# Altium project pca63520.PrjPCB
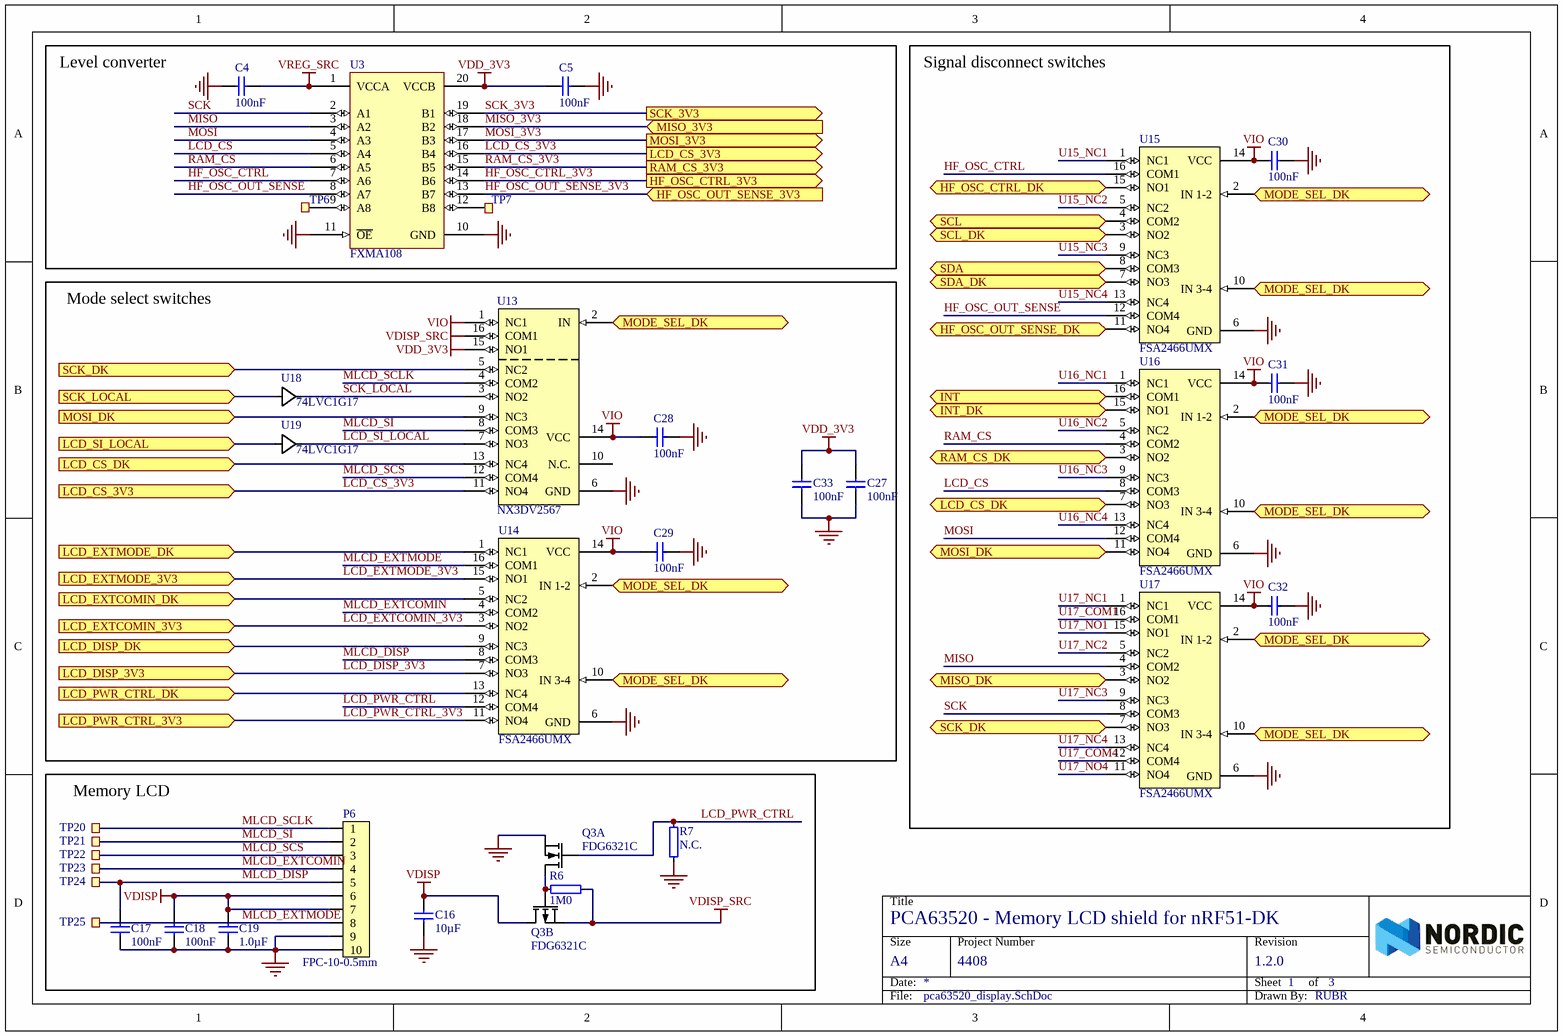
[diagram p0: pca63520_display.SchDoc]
3 sheets, 154 parts. Net scope: flat (ports and power ports of the same name join across sheets).
Board file: 400139.PcbDoc
Sheets:
  pca63520_display.SchDoc
  pca63520_interface.SchDoc
  pca63520_support_circuitry.SchDoc

## Sheet pca63520_display.SchDoc: PCA63520 - Memory LCD shield for nRF51-DK
size A4; Revision: 1.2.0; SheetNumber: 1; SheetTotal: 3; DrawnBy: RUBR; ProjectNumber: 4408; DocumentSize: A4; PCBRevision: 0233RUBR; PCAName: PCA63520; PCBNumber: 400139

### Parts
C4  100nF  [CAPC1005X04L]
C5  100nF  [CAPC1005X04L]
C16  10µF  [CAPC2012X11L]
C17  100nF  [CAPC1005X04L]
C18  100nF  [CAPC1005X04L]
C19  1.0µF  [CAPC1608X06L]
C27  100nF  [CAPC1005X04L]
C28  100nF  [CAPC1005X04L]
C29  100nF  [CAPC1005X04L]
C30  100nF  [CAPC1005X04L]
C31  100nF  [CAPC1005X04L]
C32  100nF  [CAPC1005X04L]
C33  100nF  [CAPC1005X04L]
P6  FPC-10-0.5mm  [Molex 51441-1072]
Q3  FDG6321C  [SOT65P210X100-6N]  (parts A,B of 2)
R6  1M0  [RESC1005X04L]
R7  N.C.  [RESC1005X04L]
TP6  Ø1.0mm,SMD  [TP_SMD_Ø1.0mm]  (value not drawn)  (no BOM)
TP7  Ø1.0mm,SMD  [TP_SMD_Ø1.0mm]  (value not drawn)  (no BOM)
TP20  Ø1.0mm,SMD  [TP_SMD_Ø1.0mm]  (value not drawn)  (no BOM)
TP21  Ø1.0mm,SMD  [TP_SMD_Ø1.0mm]  (value not drawn)  (no BOM)
TP22  Ø1.0mm,SMD  [TP_SMD_Ø1.0mm]  (value not drawn)  (no BOM)
TP23  Ø1.0mm,SMD  [TP_SMD_Ø1.0mm]  (value not drawn)  (no BOM)
TP24  Ø1.0mm,SMD  [TP_SMD_Ø1.0mm]  (value not drawn)  (no BOM)
TP25  Ø1.0mm,SMD  [TP_SMD_Ø1.0mm]  (value not drawn)  (no BOM)
U3  FXMA108  [QFN50P450X250X80_HS-21N]
U13  NX3DV2567  [XQFN40P180X260X50-16N]
U14  FSA2466UMX  [XQFN40P180X260X50-16N]
U15  FSA2466UMX  [XQFN40P180X260X50-16N]
U16  FSA2466UMX  [XQFN40P180X260X50-16N]
U17  FSA2466UMX  [XQFN40P180X260X50-16N]
U18  74LVC1G17  [SOT-353]
U19  74LVC1G17  [SOT-353]

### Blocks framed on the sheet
Level converter: C4 C5 TP6 TP7 U3
Signal disconnect switches: C30-C32 U15-U17
Mode select switches: C27-C29 C33 U13 U14 U18 U19
Memory LCD: C16-C19 P6 Q3 R6 R7 TP20-TP25

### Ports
HF_OSC_CTRL_3V3 (out), HF_OSC_CTRL_DK (in), HF_OSC_OUT_SENSE_3V3 (in), HF_OSC_OUT_SENSE_DK (out), INT (in), INT_DK (out), LCD_CS_3V3 (in), LCD_CS_3V3 (out), LCD_CS_DK (in), LCD_DISP_3V3 (in), LCD_DISP_DK (in), LCD_EXTCOMIN_3V3 (in), LCD_EXTCOMIN_DK (in), LCD_EXTMODE_3V3 (in), LCD_EXTMODE_DK (in), LCD_PWR_CTRL_3V3 (in), LCD_PWR_CTRL_DK (in), LCD_SI_LOCAL (in), MISO_3V3 (in), MISO_DK (out), MODE_SEL_DK (in), MOSI_3V3 (out), MOSI_DK (in), RAM_CS_3V3 (out), RAM_CS_DK (in), SCK_3V3 (out), SCK_DK (in), SCK_LOCAL (in), SCL (out), SCL_DK (in), SDA (bidir), SDA_DK (bidir)

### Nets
GND: C4.1 C5.1 C16.1 C17.1 C18.1 C19.1 C27.2 C28.1 C29.1 C30.1 C31.1 C32.1 C33.2 P6.9 P6.10 Q3.1(S1) R7.2 U3.10(GND) U3.11(~{OE}) U13.6(GND) U14.6(GND) U15.6(GND) U16.6(GND) U17.6(GND) U18.3(GND) U19.3(GND)
VDD_3V3: C5.2 C27.1 C33.1 U3.20(VCCB) U13.15(NO1) U18.5(VDD) U19.5(VDD)
VDISP: C16.2 C18.2 C19.2 P6.6 P6.7 Q3.3(D2)
VDISP_SRC: Q3.4(S2) R6.1 U13.16(COM1)
VIO: C28.2 C29.2 C30.2 C31.2 C32.2 U13.1(NC1) U13.14(VCC) U14.14(VCC) U15.14(VCC) U16.14(VCC) U17.14(VCC)
VREG_SRC: C4.2 U3.1(VCCA)
A2: U14.5(NC2) ; port LCD_EXTCOMIN_DK
A3: U14.1(NC1) ; port LCD_EXTMODE_DK
A4: U14.9(NC3) ; port LCD_DISP_DK
A5: U14.13(NC4) ; port LCD_PWR_CTRL_DK
AREF: U13.2(IN) U14.2(IN_1-2) U14.10(IN_3-4) U15.2(IN_1-2) U15.10(IN_3-4) U16.2(IN_1-2) U16.10(IN_3-4) U17.2(IN_1-2) U17.10(IN_3-4) ; port MODE_SEL_DK
D2: U15.15(NO1) ; port HF_OSC_CTRL_DK
D3: U15.11(NO4) ; port HF_OSC_OUT_SENSE_DK
D4: U16.15(NO1) ; port INT_DK
D9: U16.3(NO2) ; port RAM_CS_DK
D10 (SS): U13.13(NC4) U16.7(NO3) ; port LCD_CS_DK
D11 (MOSI): U13.9(NC3) U16.11(NO4) ; port MOSI_DK
D12 (MISO): U17.3(NO2) ; port MISO_DK
D13 (SCK): U13.5(NC2) U17.7(NO3) ; port SCK_DK
HF_OSC_CTRL: U3.7(A6) U15.16(COM1)
HF_OSC_CTRL_3V3: U3.14(B6) ; port HF_OSC_CTRL_3V3
HF_OSC_OUT_SENSE: U3.8(A7) U15.12(COM4)
HF_OSC_OUT_SENSE_3V3: U3.13(B7) ; port HF_OSC_OUT_SENSE_3V3
INT: U16.16(COM1) ; port INT
LCD_CS: U3.5(A4) U16.8(COM3)
LCD_CS_3V3: U3.16(B4) U13.11(NO4) ; port LCD_CS_3V3
LCD_DISP_3V3: U14.7(NO3) ; port LCD_DISP_3V3
LCD_EXTCOMIN_3V3: U14.3(NO2) ; port LCD_EXTCOMIN_3V3
LCD_EXTMODE_3V3: U14.15(NO1) ; port LCD_EXTMODE_3V3
LCD_PWR_CTRL: Q3.2(G1) R7.1 U14.12(COM4)
LCD_PWR_CTRL_3V3: U14.11(NO4) ; port LCD_PWR_CTRL_3V3
LCD_SI_LOCAL: U13.7(NO3) U19.4(Y)
MISO: U3.3(A2) U17.4(COM2)
MISO_3V3: U3.18(B2) ; port MISO_3V3
MLCD_DISP: C17.2 P6.5 TP24.1 U14.8(COM3)
MLCD_EXTCOMIN: P6.4 TP23.1 U14.4(COM2)
MLCD_EXTMODE: P6.8 TP25.1 U14.16(COM1)
MLCD_SCLK: P6.1 TP20.1 U13.4(COM2)
MLCD_SCS: P6.3 TP22.1 U13.12(COM4)
MLCD_SI: P6.2 TP21.1 U13.8(COM3)
MOSI: U3.4(A3) U16.12(COM4)
MOSI_3V3: U3.17(B3) ; port MOSI_3V3
RAM_CS: U3.6(A5) U16.4(COM2)
RAM_CS_3V3: U3.15(B5) ; port RAM_CS_3V3
SCK: U3.2(A1) U17.8(COM3)
SCK_3V3: U3.19(B1) ; port SCK_3V3
SCK_LOCAL: U13.3(NO2) U18.4(Y)
SCL': U15.4(COM2) ; port SCL
SCL_DK: U15.3(NO2) ; port SCL_DK
SDA': U15.8(COM3) ; port SDA
SDA_DK: U15.7(NO3) ; port SDA_DK
U15_NC1: U15.1(NC1)
U15_NC2: U15.5(NC2)
U15_NC3: U15.9(NC3)
U15_NC4: U15.13(NC4)
U16_NC1: U16.1(NC1)
U16_NC2: U16.5(NC2)
U16_NC3: U16.9(NC3)
U16_NC4: U16.13(NC4)
U17_COM1: U17.16(COM1)
U17_COM4: U17.12(COM4)
U17_NC1: U17.1(NC1)
U17_NC2: U17.5(NC2)
U17_NC3: U17.9(NC3)
U17_NC4: U17.13(NC4)
U17_NO1: U17.15(NO1)
U17_NO4: U17.11(NO4)
NetQ3_5: Q3.5(G2) Q3.6(D1) R6.2
NetTP6_1: TP6.1 U3.9(A8)
NetTP7_1: TP7.1 U3.12(B8)
NetU5_12: U19.2(A) ; port LCD_SI_LOCAL
NetU5_15: U18.2(A) ; port SCK_LOCAL

Not connected (* = marked no-connect by the designer): U13 10(N.C.); U18 1(N.C.); U19 1(N.C.)

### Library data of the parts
C4 C5 C17 C18 C27-C33 = C0402-100n: Capacitor, X7R, ±10%; Note: 16V; Artikkelnr Noca: 20039200; Artikkelnr Simpro: N.A.
C16 = C0805-10µ: Capacitor, X5R, ±10%; Note: 16V; Artikkelnr Noca: 20039243; Artikkelnr Simpro: N.A.
C19 = C0603-1µ0: Capacitor, X7R, ±10%; Note: 16V; Artikkelnr Noca: 20039335; Artikkelnr Simpro: N.A.
P6 = Molex 51441-1072: FFC/FPC Connector, Right-Angle, SMD, ZIF, Bottom Contacts, 10-way, Gold; Manufacturer: Molex; 2nd source part number: 538-51441-1072; Artikkelnr Noca: N.A.
Q3 = FDG6321C: Fairchild, FDG6321C, Dual N & P Channel Digital FET; 2nd source part number: FDG6321CCT-ND; Artikkelnr Noca: 35029089; Artikkelnr Simpro: N.A.
R6 = R0402-1M0: Resistor, ±1%, 0.063W; Note: Chip Res 1%; Artikkelnr Noca: 27049145; Artikkelnr Simpro: N.A.; Value Ohm: 1000000
R7 = R0402-N.C.: Not mounted; Note: Chip Res; Artikkelnr Noca: N.A.; Assembly: Not mounted
TP6 TP7 TP20-TP25 = TP_SMD_Ø1.0MM: 1.0mm circular SMD testpad; Manufacturer: Nordic Semiconductor; Artikkelnr Noca: N.A.
U3 = FXMA108BQX: 8-bit bidirectional voltage-level translator with auto-direction sensing; Manufacturer: Fairchild Semiconductor; 2nd source part number: 512-FXMA108BQX; Note: Translator, Bidirectional; Artikkelnr Noca: N.A.
U13 = NX3DV2567GU: Low-ohmic four-pole double-throw analog switch; Manufacturer: NXP Semiconductors; 2nd source part number: 771-NX3DV2567GU115; Artikkelnr Noca: N.A.
U14-U17 = FSA2466UMX: Data / Audio Low-Voltage Dual DPDT Analog Switch; Manufacturer: Fairchild Semiconductor; 2nd source part number: 512-FSA2466UMX; Artikkelnr Noca: N.A.
U18 U19 = 74LVC1G17SE: Single schmitt-trigger buffer with standard push-pull output; Manufacturer: Diodes; 2nd source part number: 189-3834; Artikkelnr Noca: 15049066; Artikkelnr Simpro: N.A.

## Sheet pca63520_interface.SchDoc: PCA63520 - Memory LCD shield for nRF51-DK
size A4; Revision: 1.2.0; SheetNumber: 2; SheetTotal: 3; DrawnBy: RUBR; ProjectNumber: 4408; DocumentSize: A4; PCBRevision: 0233RUBR; PCAName: PCA63520; PCBNumber: 400139
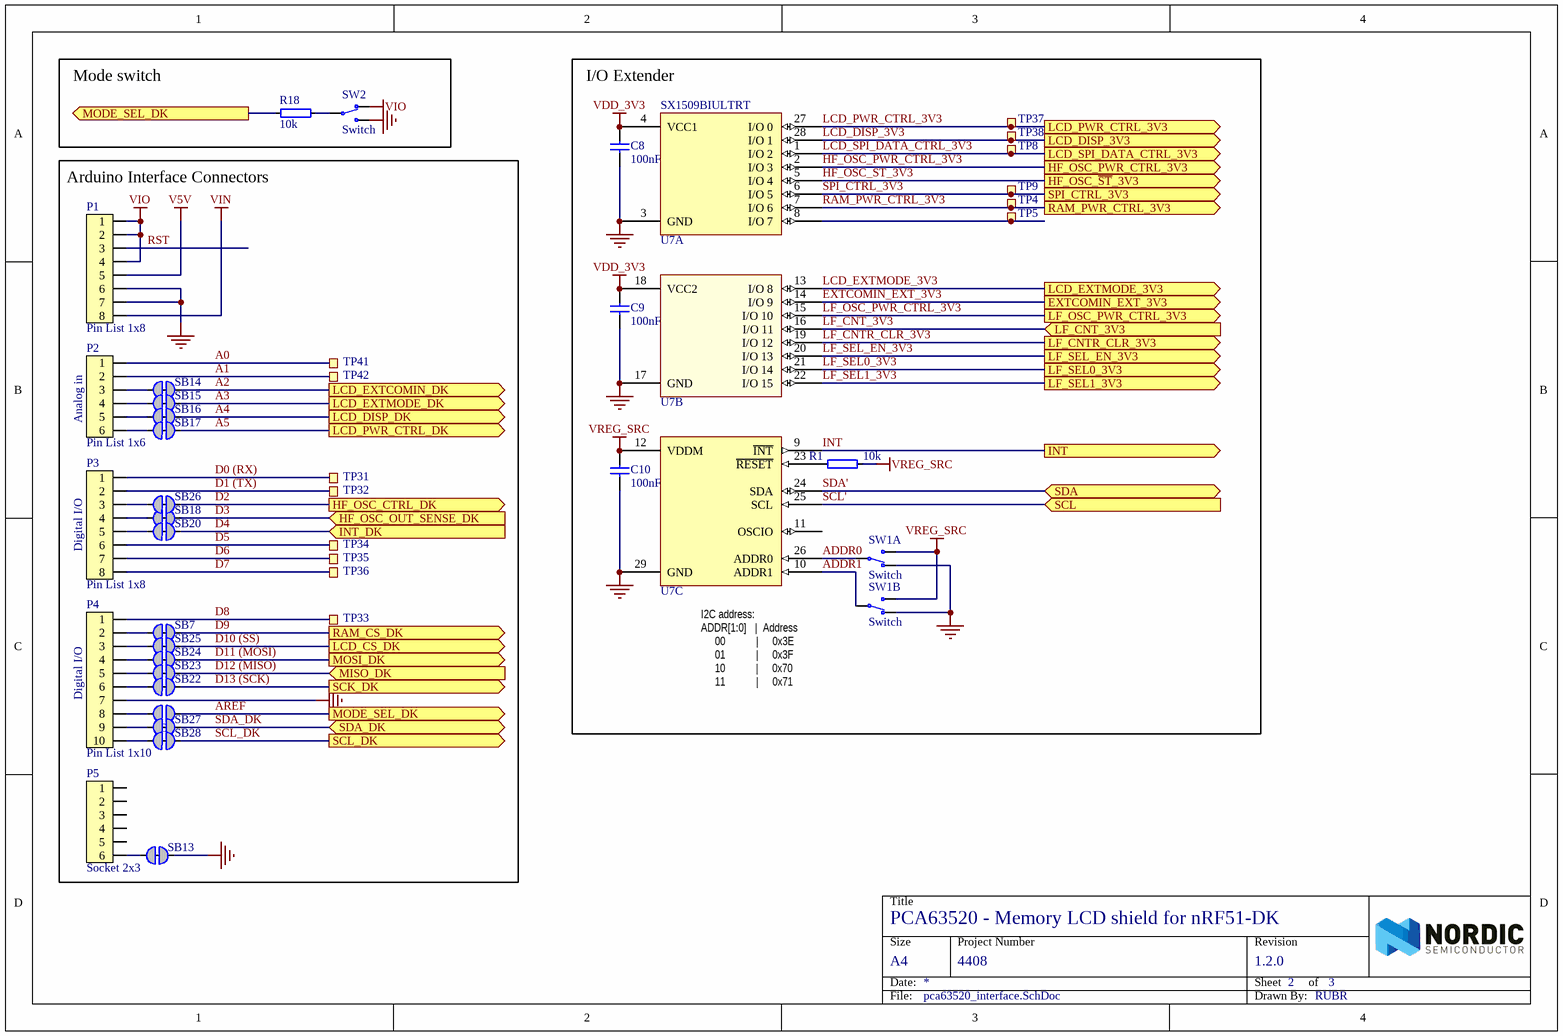
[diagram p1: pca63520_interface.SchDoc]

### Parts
C8  100nF  [CAPC1005X04L]
C9  100nF  [CAPC1005X04L]
C10  100nF  [CAPC1005X04L]
P1  Pin List 1x8  [LIST_1x8_SMD]
P2  Pin List 1x6  [LIST_1x6_SMD]
P3  Pin List 1x8  [LIST_1x8_SMD]
P4  Pin List 1x10  [LIST_1x10_SMD]
P5  Socket 2x3  [SOCKET_2x3_SMD-2.54mm-bottom]
R1  10k  [RESC1005X04L]
R18  10k  [RESC1005X04L]
SB6  Solderbridge  [Solderbridge]  (value not drawn)  (no BOM)
SB7  Solderbridge  [Solderbridge_Shorted]  (value not drawn)  (net tie, no BOM)
SB13  Solderbridge  [Solderbridge_Shorted]  (value not drawn)  (net tie, no BOM)
SB14  Solderbridge  [Solderbridge_Shorted]  (value not drawn)  (net tie, no BOM)
SB15  Solderbridge  [Solderbridge_Shorted]  (value not drawn)  (net tie, no BOM)
SB16  Solderbridge  [Solderbridge_Shorted]  (value not drawn)  (net tie, no BOM)
SB17  Solderbridge  [Solderbridge_Shorted]  (value not drawn)  (net tie, no BOM)
SB18  Solderbridge  [Solderbridge_Shorted]  (value not drawn)  (net tie, no BOM)
SB20  Solderbridge  [Solderbridge_Shorted]  (value not drawn)  (net tie, no BOM)
SB22  Solderbridge  [Solderbridge_Shorted]  (value not drawn)  (net tie, no BOM)
SB23  Solderbridge  [Solderbridge_Shorted]  (value not drawn)  (net tie, no BOM)
SB24  Solderbridge  [Solderbridge_Shorted]  (value not drawn)  (net tie, no BOM)
SB25  Solderbridge  [Solderbridge_Shorted]  (value not drawn)  (net tie, no BOM)
SB26  Solderbridge  [Solderbridge_Shorted]  (value not drawn)  (net tie, no BOM)
SB27  Solderbridge  [Solderbridge_Shorted]  (value not drawn)  (net tie, no BOM)
SB28  Solderbridge  [Solderbridge_Shorted]  (value not drawn)  (net tie, no BOM)
SW1  Switch  [CAS-D20A]  (parts A,B of 2)
SW2  Switch  [CJS-120xA]
TP4  Ø1.0mm,SMD  [TP_SMD_Ø1.0mm]  (value not drawn)  (no BOM)
TP5  Ø1.0mm,SMD  [TP_SMD_Ø1.0mm]  (value not drawn)  (no BOM)
TP8  Ø1.0mm,SMD  [TP_SMD_Ø1.0mm]  (value not drawn)  (no BOM)
TP9  Ø1.0mm,SMD  [TP_SMD_Ø1.0mm]  (value not drawn)  (no BOM)
TP31  Ø1.0mm,SMD  [TP_SMD_Ø1.0mm]  (value not drawn)  (no BOM)
TP32  Ø1.0mm,SMD  [TP_SMD_Ø1.0mm]  (value not drawn)  (no BOM)
TP33  Ø1.0mm,SMD  [TP_SMD_Ø1.0mm]  (value not drawn)  (no BOM)
TP34  Ø1.0mm,SMD  [TP_SMD_Ø1.0mm]  (value not drawn)  (no BOM)
TP35  Ø1.0mm,SMD  [TP_SMD_Ø1.0mm]  (value not drawn)  (no BOM)
TP36  Ø1.0mm,SMD  [TP_SMD_Ø1.0mm]  (value not drawn)  (no BOM)
TP37  Ø1.0mm,SMD  [TP_SMD_Ø1.0mm]  (value not drawn)  (no BOM)
TP38  Ø1.0mm,SMD  [TP_SMD_Ø1.0mm]  (value not drawn)  (no BOM)
TP41  Ø1.0mm,SMD  [TP_SMD_Ø1.0mm]  (value not drawn)  (no BOM)
TP42  Ø1.0mm,SMD  [TP_SMD_Ø1.0mm]  (value not drawn)  (no BOM)
U7  SX1509BIULTRT  [QFN40P400X400X60_HS-29N]  (parts A,B,C of 3)

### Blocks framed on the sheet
Mode switch: R18 SW2
I/O Extender: C8-C10 R1 SW1 TP4 TP5 TP8 TP9 TP37 TP38 U7
Arduino Interface Connectors: P1-P5 SB6 SB7 SB13-SB18 SB20 SB22-SB28 TP31-TP36 TP41 TP42

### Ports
EXTCOMIN_EXT_3V3 (out), HF_OSC_CTRL_DK (out), HF_OSC_OUT_SENSE_DK (in), HF_OSC_PWR_CTRL_3V3 (out), HF_OSC_~{ST}_3V3 (out), INT (out), INT_DK (in), LCD_CS_DK (out), LCD_DISP_3V3 (out), LCD_DISP_DK (out), LCD_EXTCOMIN_DK (out), LCD_EXTMODE_3V3 (out), LCD_EXTMODE_DK (out), LCD_PWR_CTRL_3V3 (out), LCD_PWR_CTRL_DK (out), LCD_SPI_DATA_CTRL_3V3 (out), LF_CNT_3V3 (in), LF_CNTR_CLR_3V3 (out), LF_OSC_PWR_CTRL_3V3 (out), LF_SEL0_3V3 (out), LF_SEL1_3V3 (out), LF_SEL_EN_3V3 (out), MISO_DK (in), MODE_SEL_DK (out), MOSI_DK (out), RAM_CS_DK (out), RAM_PWR_CTRL_3V3 (out), SCK_DK (out), SCL (in), SCL_DK (out), SDA (bidir), SDA_DK (bidir), SPI_CTRL_3V3 (out)

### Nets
GND: C8.1 C9.1 C10.1 P1.6 P1.7 P4.7 SB13.1 SW1.3(N.C) SW1.6(N.C) SW2.3(N.O) U7.3(GND) U7.17(GND) U7.29(GND)
V5V: P1.5
VDD_3V3: C8.2 C9.2 U7.4(VCC1) U7.18(VCC2)
VIN: P1.8
VIO: P1.1 P1.2 P1.4 SW2.1(N.C)
VREG_SRC: C10.2 R1.2 SW1.1(N.O) SW1.4(N.O) U7.12(VDDM)
A0: P2.1 TP41.1
A1: P2.2 TP42.1
A2: SB14.1 ; port LCD_EXTCOMIN_DK
A3: SB15.1 ; port LCD_EXTMODE_DK
A4: SB16.1 ; port LCD_DISP_DK
A5: SB17.1 ; port LCD_PWR_CTRL_DK
ADDR0: SW1.2(COM) U7.26(ADDR0)
ADDR1: SW1.5(COM) U7.10(ADDR1)
AREF: R18.1 SB6.1 ; port MODE_SEL_DK
D0 (RX): P3.1 TP31.1
D1 (TX): P3.2 TP32.1
D2: SB26.1 ; port HF_OSC_CTRL_DK
D3: SB18.1 ; port HF_OSC_OUT_SENSE_DK
D4: SB20.1 ; port INT_DK
D5: P3.6 TP34.1
D6: P3.7 TP35.1
D7: P3.8 TP36.1
D8: P4.1 TP33.1
D9: SB7.1 ; port RAM_CS_DK
D10 (SS): SB25.1 ; port LCD_CS_DK
D11 (MOSI): SB24.1 ; port MOSI_DK
D12 (MISO): SB23.1 ; port MISO_DK
D13 (SCK): SB22.1 ; port SCK_DK
EXTCOMIN_EXT_3V3: U7.14(I/O_9) ; port EXTCOMIN_EXT_3V3
HF_OSC_PWR_CTRL_3V3: U7.2(I/O_3) ; port HF_OSC_PWR_CTRL_3V3
HF_OSC_~{ST}_3V3: U7.5(I/O_4) ; port HF_OSC_~{ST}_3V3
INT: U7.9(~{INT}) ; port INT
LCD_DISP_3V3: TP38.1 U7.28(I/O_1) ; port LCD_DISP_3V3
LCD_EXTMODE_3V3: U7.13(I/O_8) ; port LCD_EXTMODE_3V3
LCD_PWR_CTRL_3V3: TP37.1 U7.27(I/O_0) ; port LCD_PWR_CTRL_3V3
LCD_SPI_DATA_CTRL_3V3: TP8.1 U7.1(I/O_2) ; port LCD_SPI_DATA_CTRL_3V3
LF_CNT_3V3: U7.16(I/O_11) ; port LF_CNT_3V3
LF_CNTR_CLR_3V3: U7.19(I/O_12) ; port LF_CNTR_CLR_3V3
LF_OSC_PWR_CTRL_3V3: U7.15(I/O_10) ; port LF_OSC_PWR_CTRL_3V3
LF_SEL0_3V3: U7.21(I/O_14) ; port LF_SEL0_3V3
LF_SEL1_3V3: U7.22(I/O_15) ; port LF_SEL1_3V3
LF_SEL_EN_3V3: U7.20(I/O_13) ; port LF_SEL_EN_3V3
RAM_PWR_CTRL_3V3: TP4.1 U7.7(I/O_6) ; port RAM_PWR_CTRL_3V3
RST: P1.3
SCL': U7.25(SCL) ; port SCL
SCL_DK: SB28.1 ; port SCL_DK
SDA': U7.24(SDA) ; port SDA
SDA_DK: SB27.1 ; port SDA_DK
SPI_CTRL_3V3: TP9.1 U7.6(I/O_5) ; port SPI_CTRL_3V3
NetP2_3: P2.3 SB14.2
NetP2_4: P2.4 SB15.2
NetP2_5: P2.5 SB16.2
NetP2_6: P2.6 SB17.2
NetP3_3: P3.3 SB26.2
NetP3_4: P3.4 SB18.2
NetP3_5: P3.5 SB20.2
NetP4_2: P4.2 SB7.2
NetP4_3: P4.3 SB25.2
NetP4_4: P4.4 SB24.2
NetP4_5: P4.5 SB23.2
NetP4_6: P4.6 SB22.2
NetP4_8: P4.8 SB6.2
NetP4_9: P4.9 SB27.2
NetP4_10: P4.10 SB28.2
NetP5_6: P5.6 SB13.2
NetR1_1: R1.1 U7.23(~{RESET})
NetR18_2: R18.2 SW2.2(COM)
NetTP5_1: TP5.1 U7.8(I/O_7)

Not connected (* = marked no-connect by the designer): P5 1 2 3 4 5; U7 11(OSCIO)

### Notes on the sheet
- (near P2) Analog in
- (near P3) Digital I/O
- (near P4) Digital I/O
- I2C address:
  ADDR[1:0]   |  Address
  00           |     0x3E
  01           |     0x3F
  10           |     0x70
  11           |     0x71

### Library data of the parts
C8-C10 = C0402-100n: as C4 on sheet pca63520_display
P1 P3 = Pin List 1x8 SMD: Pin List 1x8, 2.54mm (100mil), SMD; Manufacturer: W-CON; Manufacturer Part Number: 1125-1108S0M116R2; 2nd source part number: TSM-108-01-L-SV-P-TR; Artikkelnr Noca: 55010006; Artikkelnr Simpro: N.A.
P2 = Pin List 1x6 SMD: Pin List 1x6, 2.54mm (100mil), SMD; Manufacturer: W-CON; Manufacturer Part Number: 1125-1106S0M116R2; 2nd source part number: TSM-106-01-L-SV-P-TR; Artikkelnr Noca: 55019252; Artikkelnr Simpro: N.A.
P4 = Pin List 1x10 SMD: Pin List 1x10, 2.54mm (100mil), SMD; Manufacturer: W-CON; Manufacturer Part Number: 1125-1110S0M116R2; 2nd source part number: TSM-110-01-L-SV-P-TR; Artikkelnr Noca: 55019254; Artikkelnr Simpro: N.A.
P5 = Socket 2x3 SMD Bottom: Socket 2x3, 2.54mm (100mil), SMD; Manufacturer: W-CON; Manufacturer Part Number: 2171-203MS0CUNR1; 2nd source part number: SSM-103-F-DV-P-TR; Artikkelnr Noca: 55019255; Artikkelnr Simpro: N.A.
R1 R18 = R0402-10k: Resistor, ±1%, 0.063W; Note: Chip Res 1%; Artikkelnr Noca: 27049097; Artikkelnr Simpro: N.A.; Value Ohm: 10000
SB6 = Solderbridge: Artikkelnr Noca: N.A.
SB7 SB13-SB18 SB20 SB22-SB28 = Solderbridge Shorted: Shorted Solderbridge; Artikkelnr Noca: N.A.
SW1 = CAS-D20TA: SMD slide Switch 2xSPDT; Manufacturer: Copal Electronics Inc; Artikkelnr Noca: N.A.
SW2 = CJS-1200TA: SMD slide Switch (ON-ON); Manufacturer: Copal Electronics Inc; Artikkelnr Noca: 50019068; Artikkelnr Simpro: N.A.
TP4 TP5 TP8 TP9 TP31-TP38 TP41 TP42 = TP_SMD_Ø1.0MM: as TP6 on sheet pca63520_display
U7 = SX1509BIULTRT: IC GPIO EXPANDER I2C 16CH 28QFN; Manufacturer: Semtech Corporation; Artikkelnr Noca: N.A.

## Sheet pca63520_support_circuitry.SchDoc: PCA63520 - Memory LCD shield for nRF51-DK
size A3; Revision: 1.2.0; SheetNumber: 3; SheetTotal: 3; DrawnBy: RUBR; ProjectNumber: 4408; DocumentSize: A3; PCBRevision: 0233RUBR; PCAName: PCA63520; PCBNumber: 400139
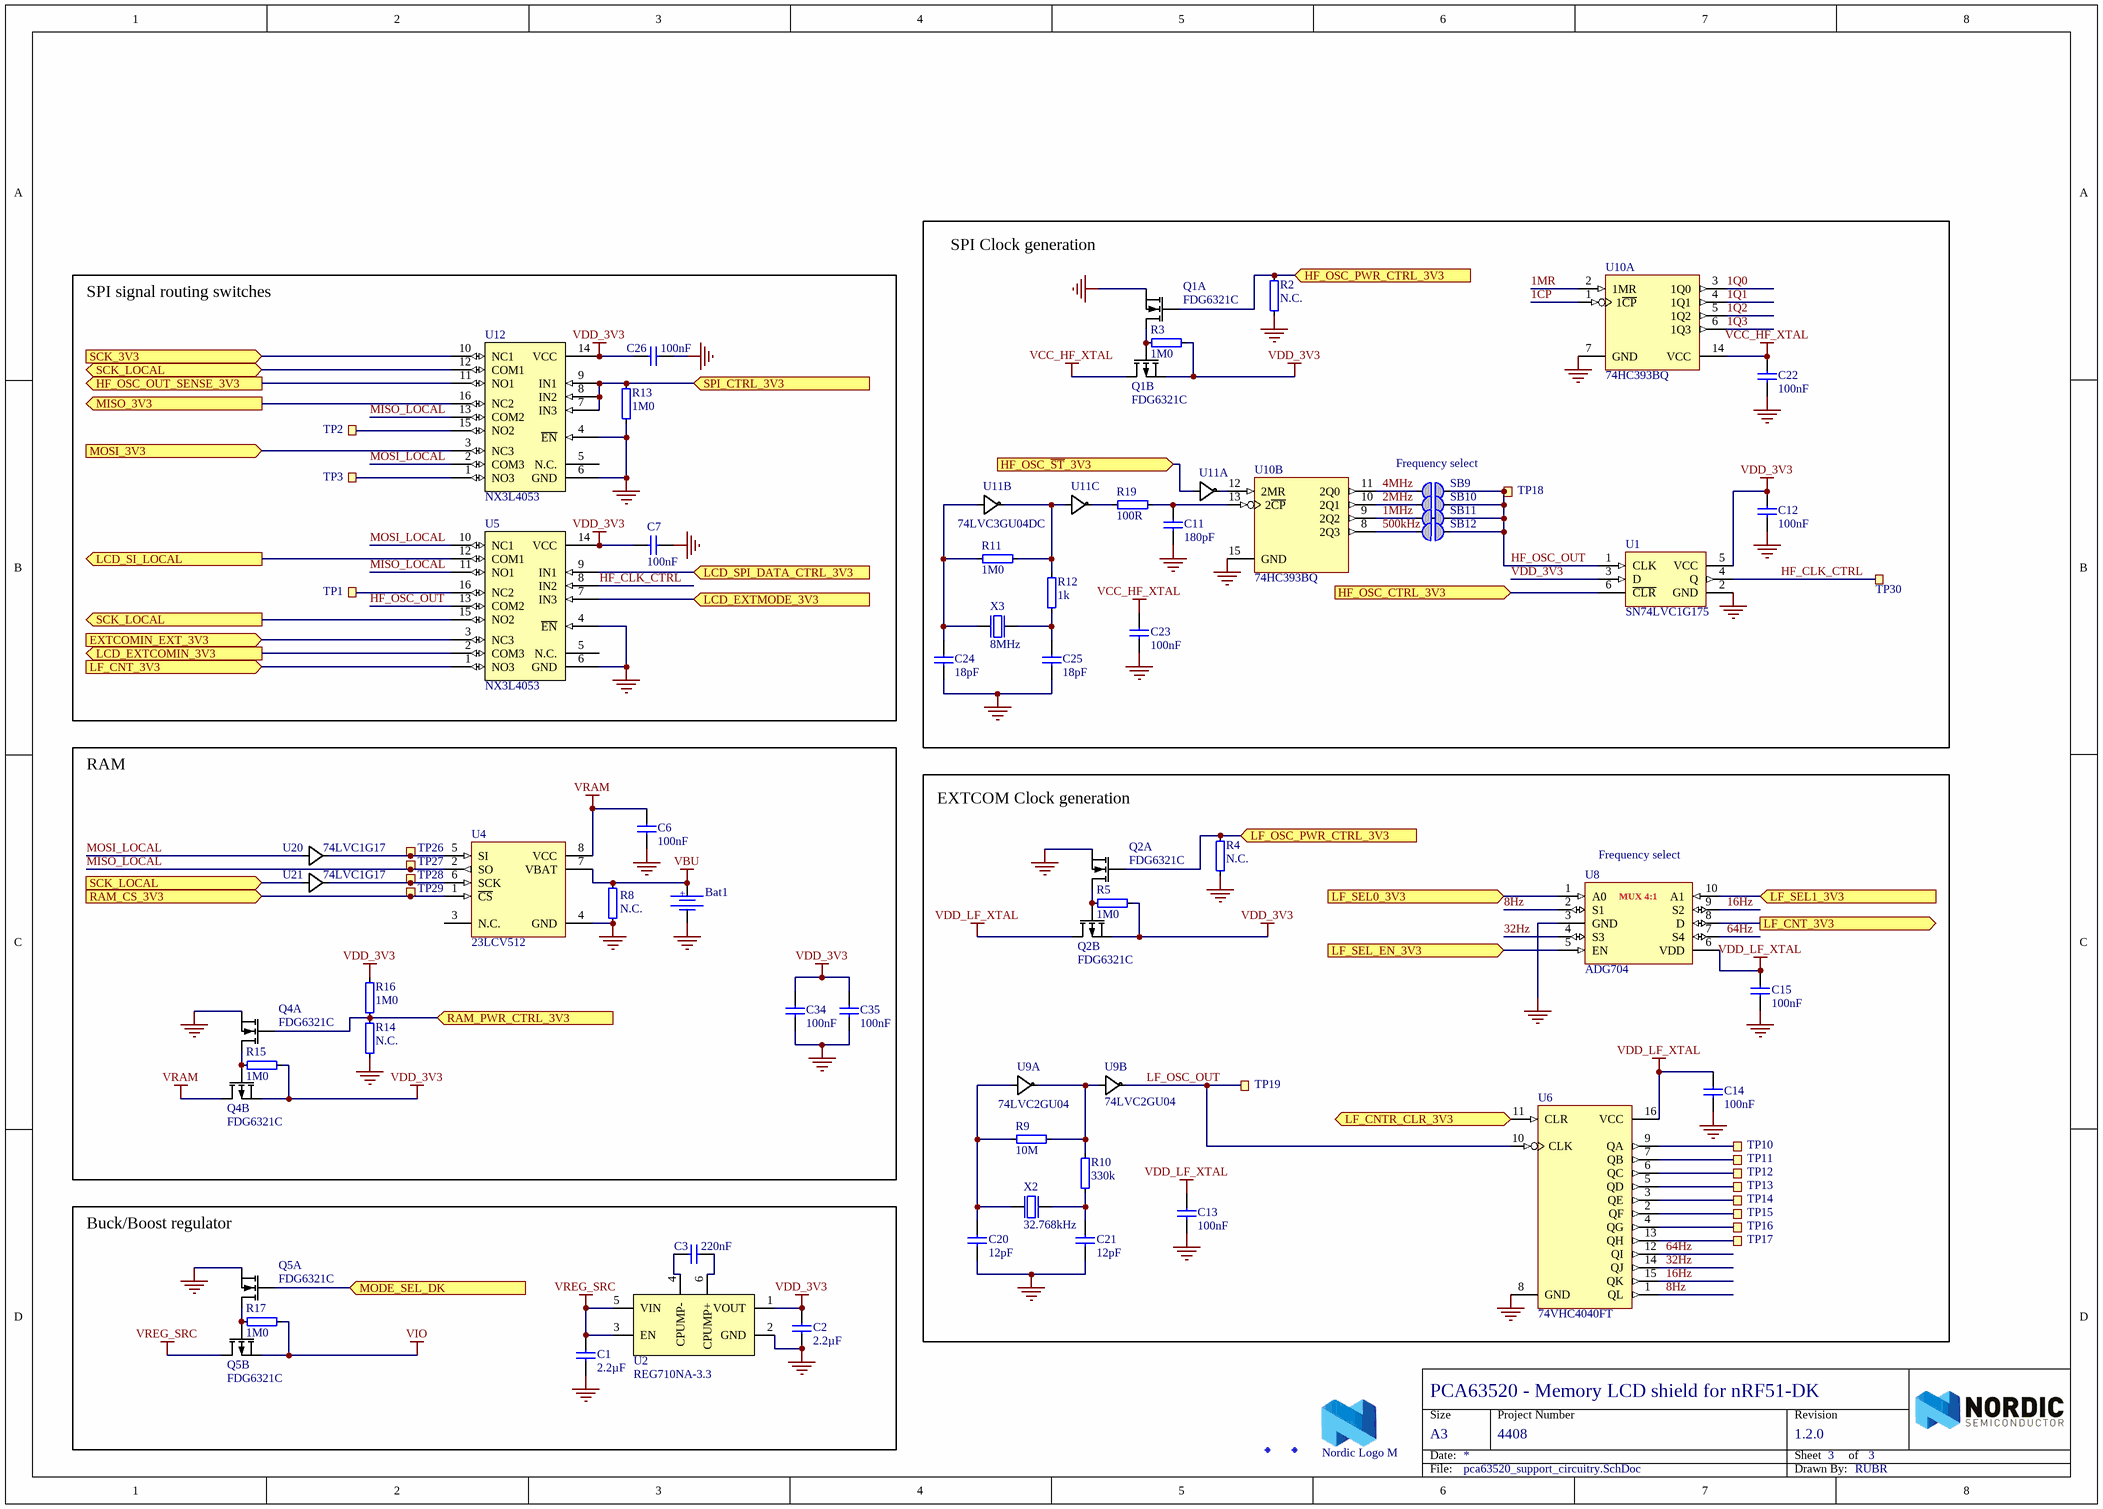
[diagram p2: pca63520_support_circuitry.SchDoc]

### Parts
Bat1  Bat Holder CR1025  [CR1025_HOLDER_SMD]  (value not drawn)
C1  2.2µF  [CAPC3216X13L]
C2  2.2µF  [CAPC3216X13L]
C3  220nF  [CAPC3216X13L]
C6  100nF  [CAPC1005X04L]
C7  100nF  [CAPC1005X04L]
C11  180pF  [CAPC1005X04L]
C12  100nF  [CAPC1005X04L]
C13  100nF  [CAPC1005X04L]
C14  100nF  [CAPC1005X04L]
C15  100nF  [CAPC1005X04L]
C20  12pF  [CAPC1005X04L]
C21  12pF  [CAPC1005X04L]
C22  100nF  [CAPC1005X04L]
C23  100nF  [CAPC1005X04L]
C24  18pF  [CAPC1005X04L]
C25  18pF  [CAPC1005X04L]
C26  100nF  [CAPC1005X04L]
C34  100nF  [CAPC1005X04L]
C35  100nF  [CAPC1005X04L]
Fid1  Fiducial mark  [Fiducial]  (value not drawn)
Fid2  Fiducial mark  [Fiducial]  (value not drawn)
LOGO1  Nordic Logo M  [NORDIC_LOGO_M]  (no BOM)
Q1  FDG6321C  [SOT65P210X100-6N]  (parts A,B of 2)
Q2  FDG6321C  [SOT65P210X100-6N]  (parts A,B of 2)
Q4  FDG6321C  [SOT65P210X100-6N]  (parts A,B of 2)
Q5  FDG6321C  [SOT65P210X100-6N]  (parts A,B of 2)
R2  N.C.  [RESC1005X04L]
R3  1M0  [RESC1005X04L]
R4  N.C.  [RESC1005X04L]
R5  1M0  [RESC1005X04L]
R8  N.C.  [RESC1005X04L]
R9  10M  [RESC1005X04L]
R10  330k  [RESC1005X04L]
R11  1M0  [RESC1005X04L]
R12  1k  [RESC1005X04L]
R13  1M0  [RESC1005X04L]
R14  N.C.  [RESC1005X04L]
R15  1M0  [RESC1005X04L]
R16  1M0  [RESC1005X04L]
R17  1M0  [RESC1005X04L]
R19  100R  [RESC1005X04L]
SB9  Solderbridge  [Solderbridge]  (value not drawn)  (no BOM)
SB10  Solderbridge  [Solderbridge]  (value not drawn)  (no BOM)
SB11  Solderbridge  [Solderbridge_Shorted]  (value not drawn)  (net tie, no BOM)
SB12  Solderbridge  [Solderbridge]  (value not drawn)  (no BOM)
TP1  Ø1.0mm,SMD  [TP_SMD_Ø1.0mm]  (value not drawn)  (no BOM)
TP2  Ø1.0mm,SMD  [TP_SMD_Ø1.0mm]  (value not drawn)  (no BOM)
TP3  Ø1.0mm,SMD  [TP_SMD_Ø1.0mm]  (value not drawn)  (no BOM)
TP10  Ø1.0mm,SMD  [TP_SMD_Ø1.0mm]  (value not drawn)  (no BOM)
TP11  Ø1.0mm,SMD  [TP_SMD_Ø1.0mm]  (value not drawn)  (no BOM)
TP12  Ø1.0mm,SMD  [TP_SMD_Ø1.0mm]  (value not drawn)  (no BOM)
TP13  Ø1.0mm,SMD  [TP_SMD_Ø1.0mm]  (value not drawn)  (no BOM)
TP14  Ø1.0mm,SMD  [TP_SMD_Ø1.0mm]  (value not drawn)  (no BOM)
TP15  Ø1.0mm,SMD  [TP_SMD_Ø1.0mm]  (value not drawn)  (no BOM)
TP16  Ø1.0mm,SMD  [TP_SMD_Ø1.0mm]  (value not drawn)  (no BOM)
TP17  Ø1.0mm,SMD  [TP_SMD_Ø1.0mm]  (value not drawn)  (no BOM)
TP18  Ø1.0mm,SMD  [TP_SMD_Ø1.0mm]  (value not drawn)  (no BOM)
TP19  Ø1.0mm,SMD  [TP_SMD_Ø1.0mm]  (value not drawn)  (no BOM)
TP26  Ø1.0mm,SMD  [TP_SMD_Ø1.0mm]  (value not drawn)  (no BOM)
TP27  Ø1.0mm,SMD  [TP_SMD_Ø1.0mm]  (value not drawn)  (no BOM)
TP28  Ø1.0mm,SMD  [TP_SMD_Ø1.0mm]  (value not drawn)  (no BOM)
TP29  Ø1.0mm,SMD  [TP_SMD_Ø1.0mm]  (value not drawn)  (no BOM)
TP30  Ø1.0mm,SMD  [TP_SMD_Ø1.0mm]  (value not drawn)  (no BOM)
U1  SN74LVC1G175  [SOT95P280X145-6N]
U2  REG710NA-3.3  [SOT95P280X145-6N]
U4  23LCV512  [TSOP65P640X120-8N]
U5  NX3L4053  [QFN50P300X300X50_HS-17N]
U6  74VHC4040FT  [TSOP65P640X110-16N]
U8  ADG704  [MSOP-10]
U9  74LVC2GU04  [SOT65P210X100-6N]  (parts A,B of 2)
U10  74HC393BQ  [QFN50P250X300X100_HS-15N]  (parts A,B of 2)
U11  74LVC3GU04DC  [TSSOP50P310X90-8N]  (value not drawn)  (parts A,B,C of 3)
U12  NX3L4053  [QFN50P300X300X50_HS-17N]
U20  74LVC1G17  [SOT-353]
U21  74LVC1G17  [SOT-353]
X2  32.768kHz  [XTAL_3215]
X3  8MHz  [BT-XTAL_5032]

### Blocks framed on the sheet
SPI Clock generation: C11 C12 C22-C25 Q1 R2 R3 R11 R12 R19 SB9-SB12 TP18 TP30 U1 U10 U11 X3
SPI signal routing switches: C7 C26 R13 TP1-TP3 U5 U12
RAM: Bat1 C6 C34 C35 Q4 R8 R14-R16 TP26-TP29 U4 U20 U21
EXTCOM Clock generation: C13-C15 C20 C21 Q2 R4 R5 R9 R10 TP10-TP17 TP19 U6 U8 U9 X2
Buck/Boost regulator: C1-C3 Q5 R17 U2

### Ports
EXTCOMIN_EXT_3V3 (in), HF_OSC_CTRL_3V3 (in), HF_OSC_OUT_SENSE_3V3 (out), HF_OSC_PWR_CTRL_3V3 (in), HF_OSC_~{ST}_3V3 (in), LCD_EXTCOMIN_3V3 (out), LCD_EXTMODE_3V3 (in), LCD_SI_LOCAL (out), LCD_SPI_DATA_CTRL_3V3 (in), LF_CNT_3V3 (in), LF_CNT_3V3 (out), LF_CNTR_CLR_3V3 (in), LF_OSC_PWR_CTRL_3V3 (in), LF_SEL0_3V3 (in), LF_SEL1_3V3 (in), LF_SEL_EN_3V3 (in), MISO_3V3 (out), MODE_SEL_DK (in), MOSI_3V3 (in), RAM_CS_3V3 (in), RAM_PWR_CTRL_3V3 (in), SCK_3V3 (in), SCK_LOCAL (bidir), SCK_LOCAL (in), SCK_LOCAL (out), SPI_CTRL_3V3 (in)

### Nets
GND: Bat1.2 C1.1 C2.1 C6.1 C7.1 C11.1 C12.1 C13.1 C14.1 C15.1 C20.2 C21.2 C22.1 C23.1 C24.2 C25.2 C26.1 C34.2 C35.2 Q1.1(S1) Q2.1(S1) Q4.1(S1) Q5.1(S1) R2.2 R4.2 R8.1 R13.1 R14.2 U1.2(GND) U2.2(GND) U4.4(GND) U5.4(~{EN}) U5.6(GND) U5.17(PAD) U6.8(GND) U8.3(GND) U9.2(GND) U10.7(GND) U10.15(GND) U11.4(GND) U12.4(~{EN}) U12.6(GND) U12.17(PAD) U20.3(GND) U21.3(GND) X3.2(GND) X3.4(GND)
VBU: Bat1.1 R8.2 U4.7(VBAT)
VCC_HF_XTAL: C22.2 C23.2 Q1.3(D2) U10.14(VCC) U11.8(VCC)
VDD_3V3: C2.2 C7.2 C12.2 C26.2 C34.1 C35.1 Q1.4(S2) Q2.4(S2) Q4.4(S2) R3.1 R5.1 R15.1 R16.1 U1.3(D) U1.5(VCC) U2.1(VOUT) U5.14(VCC) U12.14(VCC) U20.5(VDD) U21.5(VDD)
VDD_LF_XTAL: C13.2 C14.2 C15.2 Q2.3(D2) U6.16(VCC) U8.6(VDD) U9.5(VCC)
VIO: Q5.4(S2) R17.1
VRAM: C6.2 Q4.3(D2) U4.8(VCC)
VREG_SRC: C1.2 Q5.3(D2) U2.3(EN) U2.5(VIN)
1~{CP}: U10.1(1~{CP})
1MHz: SB11.2 U10.9(2Q2)
1MR: U10.2(1MR)
1Q0: U10.3(1Q0)
1Q1: U10.4(1Q1)
1Q2: U10.5(1Q2)
1Q3: U10.6(1Q3)
2MHz: SB10.2 U10.10(2Q1)
4MHz: SB9.2 U10.11(2Q0)
8Hz: U6.1(QL) U8.2(S1)
16Hz: U6.15(QK) U8.9(S2)
32Hz: U6.14(QJ) U8.4(S3)
64Hz: U6.12(QI) U8.7(S4)
500kHz: SB12.2 U10.8(2Q3)
AREF: Q5.2(G1) ; port MODE_SEL_DK
EXTCOMIN_EXT_3V3: U5.3(NC3) ; port EXTCOMIN_EXT_3V3
HF_CLK_CTRL: TP30.1 U1.4(Q) U5.8(IN2)
HF_OSC_CTRL_3V3: U1.6(~{CLR}) ; port HF_OSC_CTRL_3V3
HF_OSC_OUT: SB9.1 SB10.1 SB11.1 SB12.1 TP18.1 U1.1(CLK) U5.13(COM2)
HF_OSC_OUT_SENSE_3V3: U12.11(NO1) ; port HF_OSC_OUT_SENSE_3V3
HF_OSC_PWR_CTRL_3V3: Q1.2(G1) R2.1 ; port HF_OSC_PWR_CTRL_3V3
HF_OSC_~{ST}_3V3: U11.1(1A) ; port HF_OSC_~{ST}_3V3
LCD_EXTCOMIN_3V3: U5.2(COM3) ; port LCD_EXTCOMIN_3V3
LCD_EXTMODE_3V3: U5.7(IN3) ; port LCD_EXTMODE_3V3
LCD_SPI_DATA_CTRL_3V3: U5.9(IN1) ; port LCD_SPI_DATA_CTRL_3V3
LF_CNT_3V3: U5.1(NO3) U8.8(D) ; port LF_CNT_3V3
LF_CNTR_CLR_3V3: U6.11(CLR) ; port LF_CNTR_CLR_3V3
LF_OSC_OUT: TP19.1 U6.10(CLK) U9.4(2Y)
LF_OSC_PWR_CTRL_3V3: Q2.2(G1) R4.1 ; port LF_OSC_PWR_CTRL_3V3
LF_SEL0_3V3: U8.1(A0) ; port LF_SEL0_3V3
LF_SEL1_3V3: U8.10(A1) ; port LF_SEL1_3V3
LF_SEL_EN_3V3: U8.5(EN) ; port LF_SEL_EN_3V3
MISO_3V3: U12.16(NC2) ; port MISO_3V3
MISO_LOCAL: TP27.1 U4.2(SO) U5.11(NO1) U12.13(COM2)
MOSI_3V3: U12.3(NC3) ; port MOSI_3V3
MOSI_LOCAL: U5.10(NC1) U12.2(COM3) U20.2(A)
RAM_CS_3V3: TP29.1 U4.1(~{CS}) ; port RAM_CS_3V3
RAM_PWR_CTRL_3V3: Q4.2(G1) R14.1 R16.2 ; port RAM_PWR_CTRL_3V3
SCK_3V3: U12.10(NC1) ; port SCK_3V3
SPI_CTRL_3V3: R13.2 U12.7(IN3) U12.8(IN2) U12.9(IN1) ; port SPI_CTRL_3V3
NetC3_1: C3.1 U2.4(CPUMP-)
NetC3_2: C3.2 U2.6(CPUMP+)
NetC11_2: C11.2 R19.2 U10.13(2~{CP})
NetC20_1: C20.1 R9.1 U9.1(1A) X2.2(out)
NetC21_1: C21.1 R10.1 X2.1(inp)
NetC24_1: C24.1 R11.1 U11.3(2A) X3.1(inp)
NetC25_1: C25.1 R12.1 X3.3(out)
NetQ1_5: Q1.5(G2) Q1.6(D1) R3.2
NetQ2_5: Q2.5(G2) Q2.6(D1) R5.2
NetQ4_5: Q4.5(G2) Q4.6(D1) R15.2
NetQ5_5: Q5.5(G2) Q5.6(D1) R17.2
NetR9_2: R9.2 R10.2 U9.3(2A) U9.6(1Y)
NetR11_2: R11.2 R12.2 U11.5(2Y) U11.6(3A)
NetR19_1: R19.1 U11.2(3Y)
NetTP1_1: TP1.1 U5.16(NC2)
NetTP2_1: TP2.1 U12.15(NO2)
NetTP3_1: TP3.1 U12.1(NO3)
NetTP10_1: TP10.1 U6.9(QA)
NetTP11_1: TP11.1 U6.7(QB)
NetTP12_1: TP12.1 U6.6(QC)
NetTP13_1: TP13.1 U6.5(QD)
NetTP14_1: TP14.1 U6.3(QE)
NetTP15_1: TP15.1 U6.2(QF)
NetTP16_1: TP16.1 U6.4(QG)
NetTP17_1: TP17.1 U6.13(QH)
NetTP26_1: TP26.1 U4.5(SI) U20.4(Y)
NetTP28_1: TP28.1 U4.6(SCK) U21.4(Y)
NetU5_12: U5.12(COM1) ; port LCD_SI_LOCAL
NetU5_15: U5.15(NO2) U12.12(COM1) U21.2(A) ; port SCK_LOCAL
NetU10_12: U10.12(2MR) U11.7(1Y)

Not connected (* = marked no-connect by the designer): U4 3(N.C.); U5 5(N.C.); U12 5(N.C.); U20 1(N.C.); U21 1(N.C.)

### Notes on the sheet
- Frequency select
- (near U8) Frequency select

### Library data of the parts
Bat1 = Bat Holder CR1025 SMD: Manufacturer: Keystone; Manufacturer Part Number: 3030; Artikkelnr Noca: N.A.
C1 C2 = C1206-2µ2: Capacitor, X7R, ±10%; Note: 16V; Artikkelnr Noca: 20039142; Artikkelnr Simpro: N.A.
C3 = C0805-220n: Capacitor, X7R, ±10%; Part Number: C1206-220n; Note: 16V; Artikkelnr Noca: N.A.
C6 C7 C12-C15 C22 C23 C26 C34 C35 = C0402-100n: as C4 on sheet pca63520_display
C11 = C0402-180p: Capacitor, NP0, ±5%; Note: 50V; Artikkelnr Noca: 20029218; Artikkelnr Simpro: N.A.
C20 C21 = C0402-12p: Capacitor, NP0, ±2%; Note: 50V; Artikkelnr Noca: 20029159; Artikkelnr Simpro: N.A.
C24 C25 = C0402-18p: Capacitor, NP0, ±5%; Note: 50V; Artikkelnr Noca: 20029209; Artikkelnr Simpro: N.A.
Fid1 Fid2 = Fid-Mark: Artikkelnr Noca: N.A.
LOGO1 = Nordic Logo M: Nordic Logo, medium size; Artikkelnr Noca: N.A.
Q1 Q2 Q4 Q5 = FDG6321C: as Q3 on sheet pca63520_display
R2 R4 R8 R14 = R0402-N.C.: as R7 on sheet pca63520_display
R3 R5 R11 R13 R15-R17 = R0402-1M0: as R6 on sheet pca63520_display
R9 = R0402-10M: Resistor, ±1%, 0.063W; Note: Chip Res 1%; Artikkelnr Noca: 27049169; Artikkelnr Simpro: N.A.; Value Ohm: 10000000
R10 = R0402-330k: Resistor, ±1%, 0.063W; Note: Chip Res 1%; Artikkelnr Noca: 27049133; Artikkelnr Simpro: N.A.; Value Ohm: 330000
R12 = R0402-1K0: Resistor, ±1%, 0.063W; Note: Chip Res 1%; Artikkelnr Noca: 27049073; Artikkelnr Simpro: N.A.; Value Ohm: 1000
R19 = R0402-100: Resistor, ±1%, 0.063W; Note: Chip Res 1%; Artikkelnr Noca: 27049049; Artikkelnr Simpro: N.A.; Value Ohm: 100
SB9 SB10 SB12 = Solderbridge: Artikkelnr Noca: N.A.
SB11 = Solderbridge Shorted: as SB7 on sheet pca63520_interface
TP1-TP3 TP10-TP19 TP26-TP30 = TP_SMD_Ø1.0MM: as TP6 on sheet pca63520_display
U1 = SN74LVC1G175DBVR: Single D-Type Flip-Flop With Asynchronous Clear; Manufacturer: Texas Instruments; Artikkelnr Noca: N.A.
U2 = REG710NA-3.3: IC MULTI CONFG 3.3V 30MA SOT23-6; Manufacturer: Texas Instruments; Manufacturer Part Number: REG710NA-3.3/250; 2nd source part number: 296-12135-1-ND; Note: 60mA, 5.0V, Buck/Boost Charge Pump in ThinSOT-23; Artikkelnr Noca: N.A.
U4 = 23LCV512-I/ST: 512 kbit SPI Serial SRAM with Battery Backup and SDI Interface; Manufacturer: Microchip; 2nd source part number: 230-9514; Artikkelnr Noca: N.A.
U5 U12 = NX3L4053HR: Triple low-ohmic single-pole double-throw analog switch; Manufacturer: NXP Semiconductors; 2nd source part number: 771-NX3L4053HR115; Artikkelnr Noca: 15079258; Artikkelnr Simpro: N.A.
U6 = 74VHC4040FT: 12-Stage Ripple Carry Binary Counter; Manufacturer: Toshiba; Artikkelnr Noca: N.A.
U8 = ADG704BRMZ: IC MUX 4-CH 1.8/5.5V 10MSOP; Manufacturer: Analog Devices; Note: 4:1 Analog MUX, ( RM-10, UMAX-10 ); Artikkelnr Noca: N.A.
U9 = 74LVC2GU04: Dual Inverter; Manufacturer: NXP Semiconductors; Artikkelnr Noca: N.A.
U10 = 74HC393BQ: Dual 4-bit binary ripple counter; Manufacturer: NXP Semiconductors; Artikkelnr Noca: N.A.
U11 = 74LVC3GU04DC,125: Triple Inverter; Manufacturer: NXP; Artikkelnr Noca: N.A.
U20 U21 = 74LVC1G17SE: as U18 on sheet pca63520_display
X2 = XTAL_FC-135 32.768k: EPSON TOYOCOM - FC-135 32.768KHZ ±20PPM,9.0PF - CRYSTAL, SM, WATCH; 2nd source part number: 127-8037; Note: XTAL SMD 32.768kHz, 3215; Artikkelnr Noca: 22019091; Artikkelnr Simpro: N.A.
X3 = XTAL_SMD5032_8MHz_18pF_TXC: XTAL SMD 5032, 8MHz, Cl=18pF, Tol: ±30ppm, Stab: ±30ppm; Manufacturer: TXC Corporation; Manufacturer Part Number: 7B-8.000MAAJ-T; 2nd source part number: 717-7B-8.000MAAJ-T; Note: XTAL SMD 8MHz; Artikkelnr Noca: N.A.

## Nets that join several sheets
GND: pca63520_display (26 pins), pca63520_interface (13 pins), pca63520_support_circuitry (47 pins)
VDD_3V3: pca63520_display (7 pins), pca63520_interface (C8.2 C9.2 U7.4 U7.18), pca63520_support_circuitry (20 pins)
VIO: pca63520_display (11 pins), pca63520_interface (P1.1 P1.2 P1.4 SW2.1), pca63520_support_circuitry (Q5.4 R17.1)
VREG_SRC: pca63520_display (C4.2 U3.1), pca63520_interface (5 pins), pca63520_support_circuitry (C1.2 Q5.3 U2.3 U2.5)
A2: pca63520_display (U14.5), pca63520_interface (SB14.1)
A3: pca63520_display (U14.1), pca63520_interface (SB15.1)
A4: pca63520_display (U14.9), pca63520_interface (SB16.1)
A5: pca63520_display (U14.13), pca63520_interface (SB17.1)
AREF: pca63520_display (9 pins), pca63520_interface (R18.1 SB6.1), pca63520_support_circuitry (Q5.2)
D2: pca63520_display (U15.15), pca63520_interface (SB26.1)
D3: pca63520_display (U15.11), pca63520_interface (SB18.1)
D4: pca63520_display (U16.15), pca63520_interface (SB20.1)
D9: pca63520_display (U16.3), pca63520_interface (SB7.1)
D10 (SS): pca63520_display (U13.13 U16.7), pca63520_interface (SB25.1)
D11 (MOSI): pca63520_display (U13.9 U16.11), pca63520_interface (SB24.1)
D12 (MISO): pca63520_display (U17.3), pca63520_interface (SB23.1)
D13 (SCK): pca63520_display (U13.5 U17.7), pca63520_interface (SB22.1)
EXTCOMIN_EXT_3V3: pca63520_interface (U7.14), pca63520_support_circuitry (U5.3)
HF_OSC_CTRL_3V3: pca63520_display (U3.14), pca63520_support_circuitry (U1.6)
HF_OSC_OUT_SENSE_3V3: pca63520_display (U3.13), pca63520_support_circuitry (U12.11)
HF_OSC_PWR_CTRL_3V3: pca63520_interface (U7.2), pca63520_support_circuitry (Q1.2 R2.1)
HF_OSC_~{ST}_3V3: pca63520_interface (U7.5), pca63520_support_circuitry (U11.1)
INT: pca63520_display (U16.16), pca63520_interface (U7.9)
LCD_DISP_3V3: pca63520_display (U14.7), pca63520_interface (TP38.1 U7.28)
LCD_EXTCOMIN_3V3: pca63520_display (U14.3), pca63520_support_circuitry (U5.2)
LCD_EXTMODE_3V3: pca63520_display (U14.15), pca63520_interface (U7.13), pca63520_support_circuitry (U5.7)
LCD_PWR_CTRL_3V3: pca63520_display (U14.11), pca63520_interface (TP37.1 U7.27)
LCD_SPI_DATA_CTRL_3V3: pca63520_interface (TP8.1 U7.1), pca63520_support_circuitry (U5.9)
LF_CNT_3V3: pca63520_interface (U7.16), pca63520_support_circuitry (U5.1 U8.8)
LF_CNTR_CLR_3V3: pca63520_interface (U7.19), pca63520_support_circuitry (U6.11)
LF_OSC_PWR_CTRL_3V3: pca63520_interface (U7.15), pca63520_support_circuitry (Q2.2 R4.1)
LF_SEL0_3V3: pca63520_interface (U7.21), pca63520_support_circuitry (U8.1)
LF_SEL1_3V3: pca63520_interface (U7.22), pca63520_support_circuitry (U8.10)
LF_SEL_EN_3V3: pca63520_interface (U7.20), pca63520_support_circuitry (U8.5)
MISO_3V3: pca63520_display (U3.18), pca63520_support_circuitry (U12.16)
MOSI_3V3: pca63520_display (U3.17), pca63520_support_circuitry (U12.3)
NetU5_12: pca63520_display (U19.2), pca63520_support_circuitry (U5.12)
NetU5_15: pca63520_display (U18.2), pca63520_support_circuitry (U5.15 U12.12 U21.2)
RAM_CS_3V3: pca63520_display (U3.15), pca63520_support_circuitry (TP29.1 U4.1)
RAM_PWR_CTRL_3V3: pca63520_interface (TP4.1 U7.7), pca63520_support_circuitry (Q4.2 R14.1 R16.2)
SCK_3V3: pca63520_display (U3.19), pca63520_support_circuitry (U12.10)
SCL': pca63520_display (U15.4), pca63520_interface (U7.25)
SCL_DK: pca63520_display (U15.3), pca63520_interface (SB28.1)
SDA': pca63520_display (U15.8), pca63520_interface (U7.24)
SDA_DK: pca63520_display (U15.7), pca63520_interface (SB27.1)
SPI_CTRL_3V3: pca63520_interface (TP9.1 U7.6), pca63520_support_circuitry (R13.2 U12.7 U12.8 U12.9)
